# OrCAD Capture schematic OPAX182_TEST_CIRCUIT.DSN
size A; title: OPAx182 36-V, 5-MHz, Low-Noise, Zero-Drift, MUX-Friendly,; rev: 1.2; note: Datasheet: SBOS936D  EVM: N/A
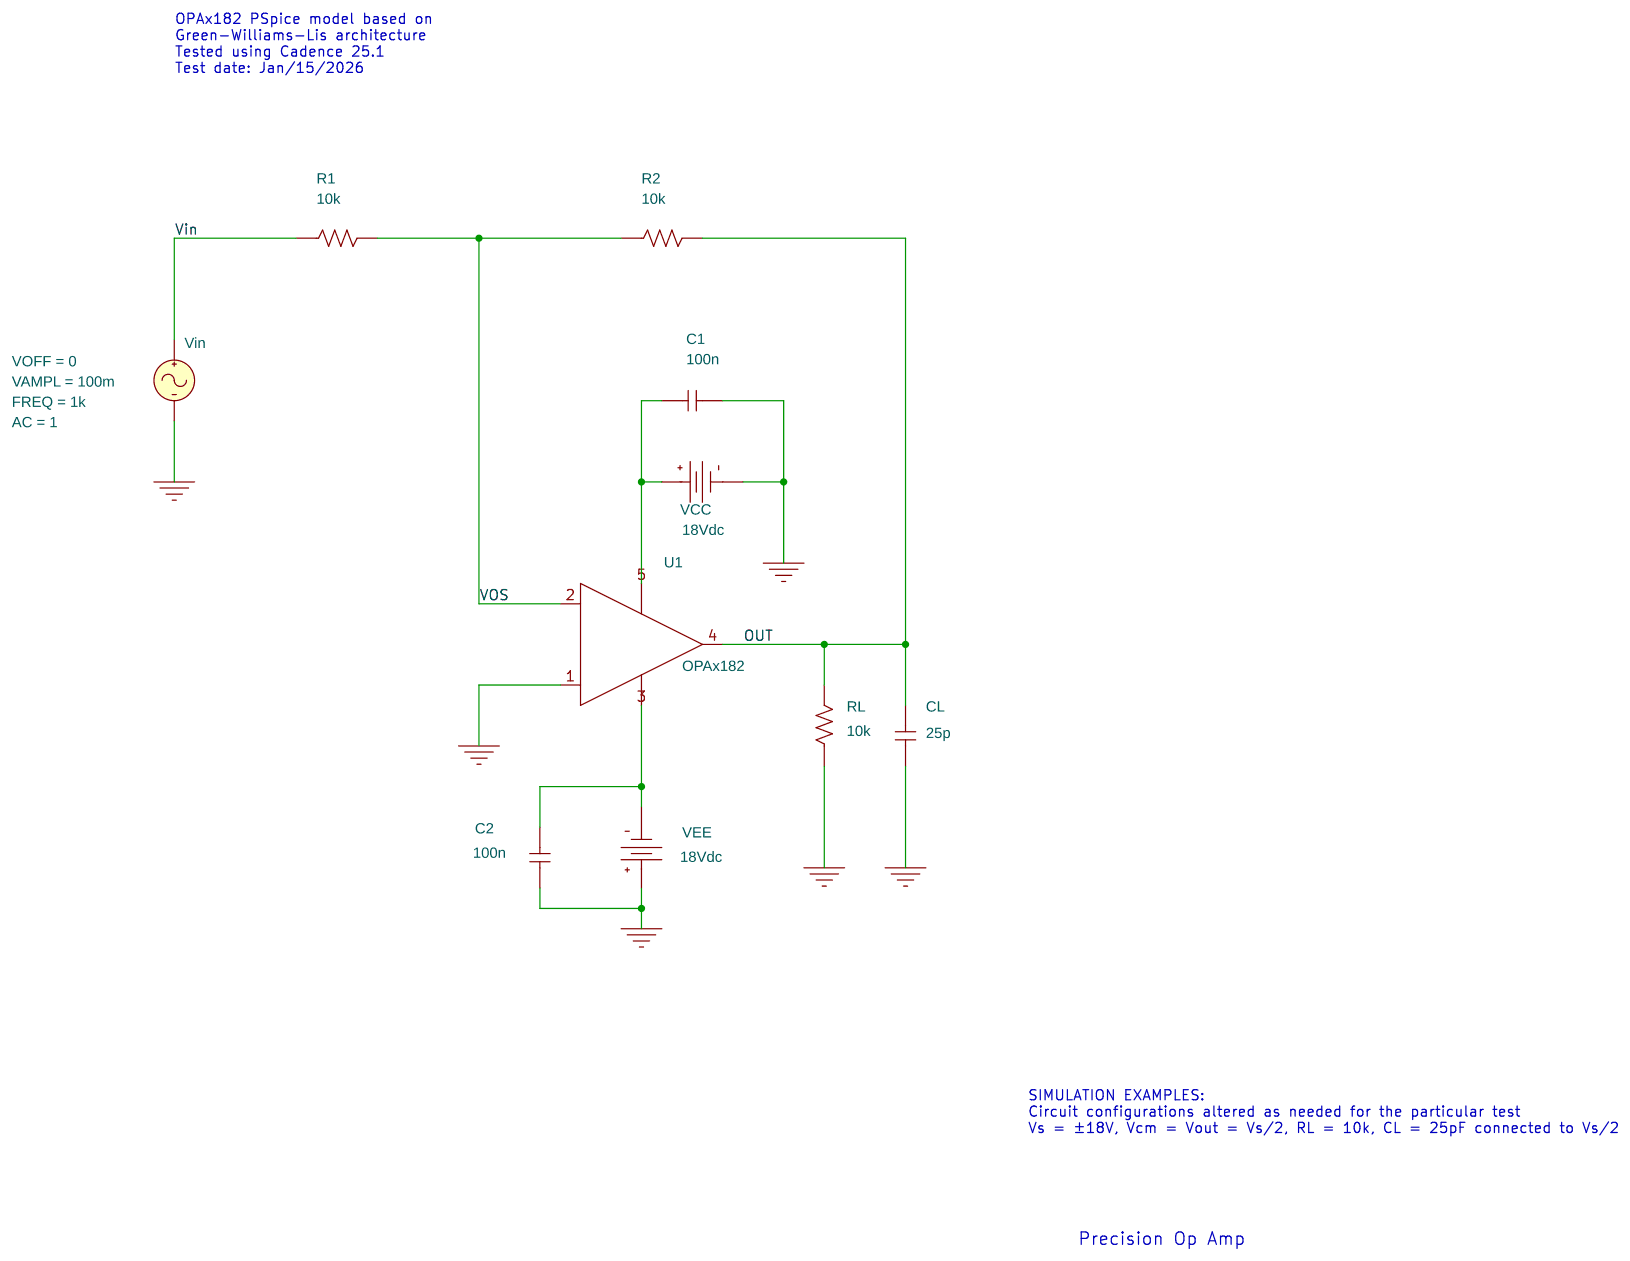
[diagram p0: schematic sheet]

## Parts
C1  100n  [cap196]
C2  100n  [cap196]
CL  25p  [cap196]
R1  10k  [AXRC05]
R2  10k  [AXRC05]
RL  10k  [AXRC05]
U1  OPAx182
VCC  VDC
VEE  VDC
Vin  VSIN

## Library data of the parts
C1 C2 CL = C
R1 R2 RL = R
U1 = OPAx182
VCC VEE = VDC: DC: 18Vdc
Vin = VSIN: AC: 1; FREQ: 1k; VAMPL: 100m; VOFF: 0

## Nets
Vin: R1.1 Vin.1(+)
0: C1.2 C2.1 CL.2 RL.1 U1.1(+) VCC.1(-) VEE.0(+) Vin.2(-)
OUT: CL.1 R2.2 RL.2 U1.4(OUT)
VOS: R1.2 R2.1 U1.2(-)
N27303: C1.1 U1.5(V+) VCC.0(+)
N27354: C2.2 U1.3(V-) VEE.1(-)

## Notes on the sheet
- OPAx182 PSpice model based on
  Green-Williams-Lis architecture
  Tested using Cadence 25.1
  Test date: Jan/15/2026
- SIMULATION EXAMPLES:
  Circuit configurations altered as needed for the particular test
  Vs = ±18V, Vcm = Vout = Vs/2, RL = 10k, CL = 25pF connected to Vs/2
- Precision Op Amp
